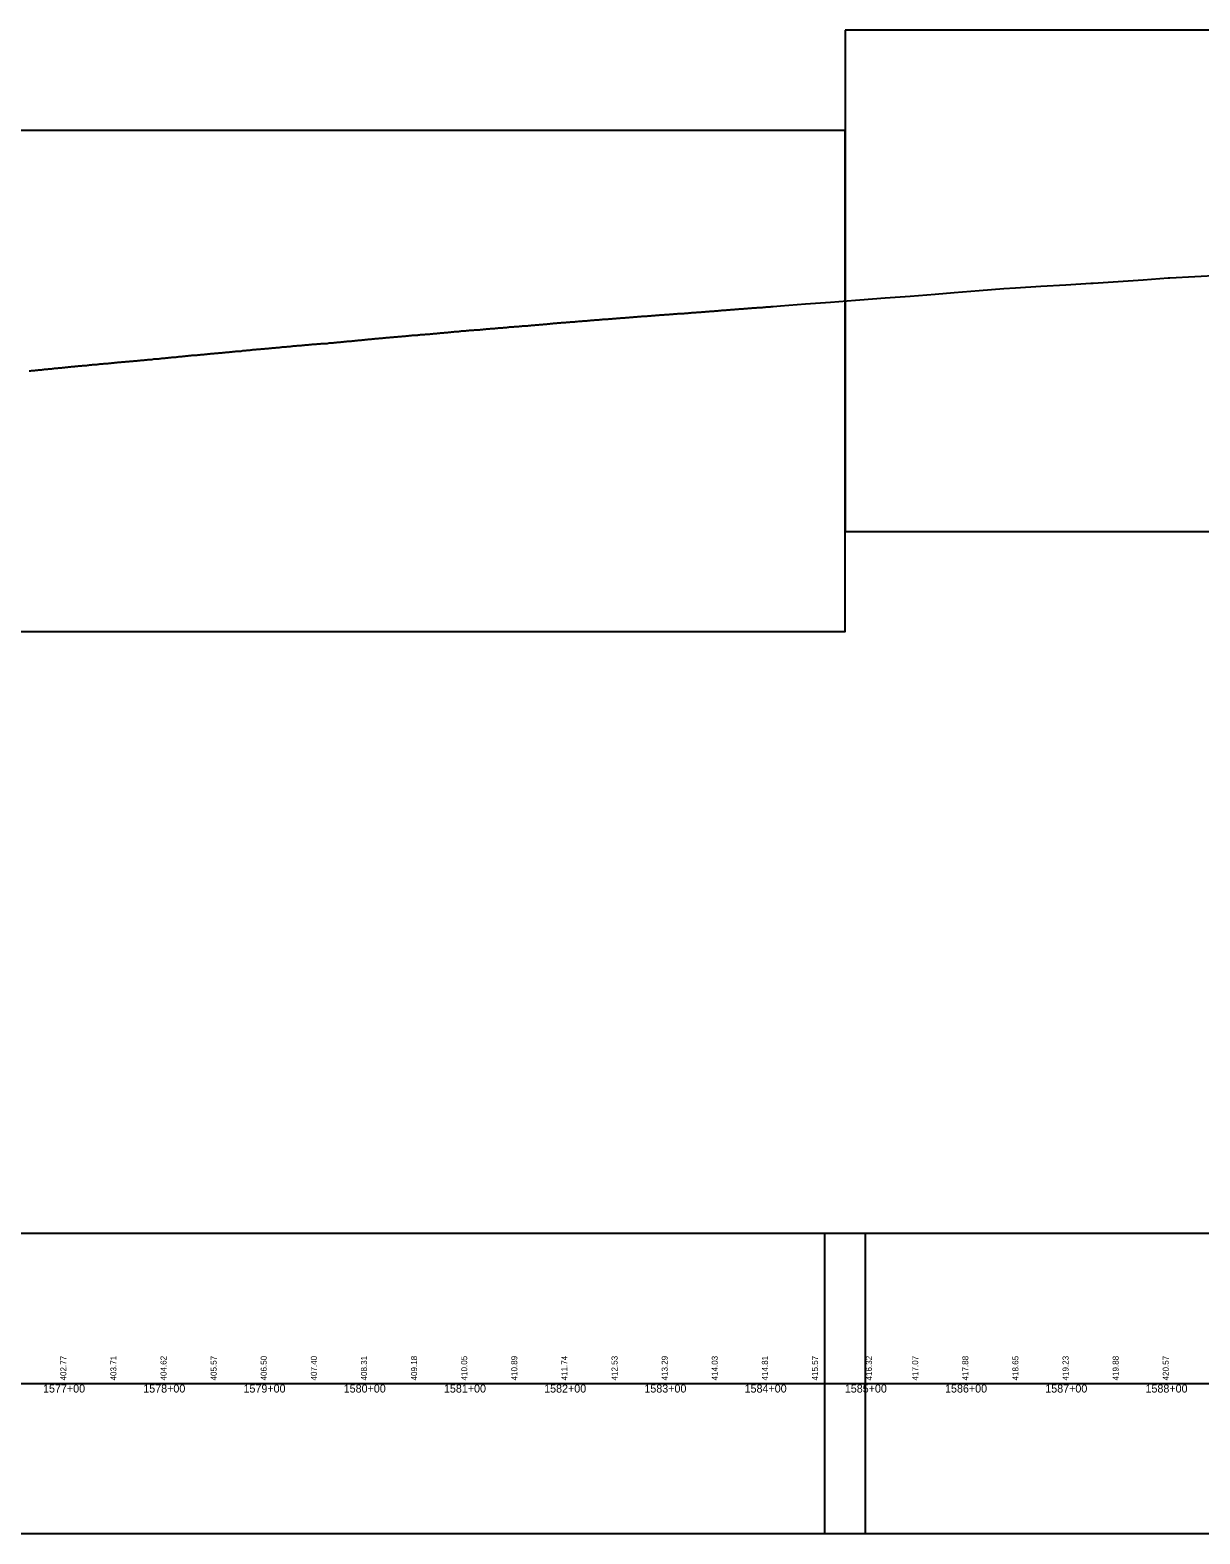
# Model space of a CAD drawing. Extents: x -3627 to 47473, y 2850 to 4350.
# Drawn here: x 45140 to 46307, y 2850 to 4350 of the extents above; entities that cross this region are included whole.
import ezdxf

# ---------------------------------------------------------------- set-up
doc = ezdxf.new("R2010")
doc.units = 0
for name, color, linetype in [('RD_DDB_Profile_EX', 7, 'Continuous'), ('RD_DDB_StaTX', 7, 'Continuous'), ('RD_DDB_StripGrade', 7, 'Continuous'), ('RD_GPK_Profile_Cell', 7, 'Continuous'), ('RD_SHT_ShtClip', 7, 'Continuous')]:
    doc.layers.add(name, color=color, linetype=linetype)

msp = doc.modelspace()

# ---------------------------------------------------------------- linework, layer by layer
at = {"layer": 'RD_DDB_Profile_EX'}
for points in [[(45795.550002, 4067.69308), (45796.552306, 4067.794065), (45797.554121, 4067.893445), (45798.555935, 4067.94337), (45799.547767, 4068.09222), (45800.549582, 4068.14269), (45801.551396, 4068.24261), (45802.5537, 4068.29309), (45803.555515, 4068.34301), (45804.547341, 4068.3935), (45805.549161, 4068.492335), (45806.550976, 4068.64169), (45807.55279, 4068.643275), (45808.555094, 4068.64372), (45809.54692, 4068.742095), (45810.54874, 4068.889875), (45811.550555, 4068.94299), (45812.55237, 4068.992905), (45813.554184, 4069.09282), (45814.5465, 4069.144365), (45815.548319, 4069.24378), (45816.550134, 4069.29423), (45817.551949, 4069.393625), (45818.553764, 4069.493015), (45819.54559, 4069.592965), (45820.547899, 4069.593455), (45821.549713, 4069.64388), (45822.551528, 4069.793285), (45823.553343, 4069.843205), (45824.545274, 4069.89368), (45825.546989, 4069.99361), (45826.549293, 4070.09356), (45827.551107, 4070.14398), (45828.552922, 4070.243395), (45829.54485, 4070.242835), (45830.546568, 4070.491195), (45831.548383, 4070.541085), (45832.550686, 4070.543665), (45833.552501, 4070.593585), (45834.544427, 4070.74254), (45835.546147, 4070.792955), (45836.547962, 4070.892355), (45837.549777, 4070.94226), (45838.551591, 4071.043205), (45839.543523, 4071.14316), (45840.545726, 4071.144135), (45841.547541, 4071.24406), (45842.549356, 4071.39348), (45843.551171, 4071.49238), (45844.543099, 4071.542835), (45845.544812, 4071.64223), (45846.546632, 4071.69214), (45847.548446, 4071.792045), (45848.550261, 4071.79356), (45849.542196, 4071.94189), (45850.543902, 4072.04125), (45851.545723, 4072.092815), (45852.547538, 4072.190495), (45853.54984, 4072.2906), (45854.541772, 4072.342635), (45855.543481, 4072.44255), (45856.545301, 4072.492465), (45857.547116, 4072.492375), (45858.548931, 4072.543385), (45859.550746, 4072.692195), (45860.542685, 4072.8399), (45861.544393, 4072.94036), (45862.546208, 4072.9414), (45863.548023, 4072.9413), (45864.549838, 4073.090035), (45865.542261, 4073.1918), (45866.543972, 4073.14337), (45867.545787, 4073.193295), (45868.547602, 4073.34265), (45869.549417, 4073.391995), (45870.541358, 4073.39252), (45871.543064, 4073.54128), (45872.544879, 4073.641185), (45873.546694, 4073.740495), (45874.548509, 4073.840395), (45875.540456, 4073.840935), (45876.542156, 4073.99024), (45877.544457, 4074.04083), (45878.546272, 4074.09073), (45879.548087, 4074.14121), (45880.540032, 4074.191745), (45881.594843, 4074.294045), (45888.780672, 4074.97893), (45913.763005, 4076.852285), (45938.745129, 4078.72374), (45963.647427, 4080.5908), (45968.230105, 4080.934145), (45993.281873, 4082.81585), (46018.333033, 4084.69476), (46043.278015, 4086.56593), (46062.121382, 4088.14348), (46087.023542, 4090.238335), (46111.893097, 4092.339635), (46123.551462, 4093.019715), (46148.601326, 4094.48206), (46173.651147, 4095.943915)], [(46173.651147, 4095.943915), (46198.528244, 4097.394905), (46200.927912, 4097.56048), (46225.893705, 4099.29392), (46250.859283, 4101.032775), (46275.748102, 4102.767855), (46277.398266, 4102.858735), (46302.414492, 4104.257475), (46327.430679, 4105.65699)], [(45695.564334, 4060.14384), (45696.556229, 4060.24377), (45697.558045, 4060.29436), (45698.559789, 4060.34426), (45699.561603, 4060.543425), (45700.563418, 4060.59368), (45701.555319, 4060.59399), (45702.557135, 4060.693505), (45703.558873, 4060.89301), (45704.560687, 4060.9925), (45705.562502, 4060.99318), (45706.554892, 4061.04422), (45707.556708, 4061.09412), (45708.55852, 4061.193635), (45709.560259, 4061.293525), (45710.562074, 4061.44303), (45711.563888, 4061.54252), (45712.555794, 4061.592445), (45713.557609, 4061.49475), (45714.559343, 4061.545485), (45715.561157, 4061.793745), (45716.562971, 4061.794075), (45717.554887, 4061.8936), (45718.556703, 4062.042635), (45719.558431, 4062.093405), (45720.560245, 4062.142865), (45721.562059, 4062.24231), (45722.553976, 4062.3427), (45723.555797, 4062.392605), (45724.557519, 4062.44297), (45725.559825, 4062.5931), (45726.561639, 4062.69256), (45727.553554, 4062.643375), (45728.555369, 4062.744175), (45729.557094, 4062.94273), (45730.558913, 4062.992175), (45731.560728, 4063.04253), (45732.552648, 4063.09341), (45733.554463, 4063.14332), (45734.556183, 4063.24323), (45735.557997, 4063.29363), (45736.559816, 4063.343555), (45737.551742, 4063.294505), (45738.553558, 4063.542915), (45739.555272, 4063.64231), (45740.557086, 4063.741695), (45741.558901, 4063.791595), (45742.550838, 4063.8426), (45743.553135, 4063.89312), (45744.554851, 4063.99253), (45745.556666, 4064.09193), (45746.55848, 4064.19183), (45747.560295, 4064.24224), (45748.55223, 4064.292195), (45749.553941, 4064.342625), (45750.555755, 4064.491465), (45751.55757, 4064.541365), (45752.559384, 4064.541805), (45753.55132, 4064.6912), (45754.553025, 4064.741655), (45755.554845, 4064.791565), (45756.55666, 4064.84204), (45757.558475, 4064.94195), (45758.550417, 4064.991895), (45759.552116, 4065.09122), (45760.55393, 4065.190535), (45761.555751, 4065.241035), (45762.558054, 4065.291595), (45763.549993, 4065.44041), (45764.551695, 4065.49144), (45765.55351, 4065.54192), (45766.555324, 4065.690665), (45767.557145, 4065.74116), (45768.549089, 4065.841105), (45769.550786, 4065.891005), (45770.5526, 4065.99091), (45771.554415, 4065.991425), (45772.556718, 4066.04252), (45773.54866, 4066.141895), (45774.550365, 4066.24181), (45775.55218, 4066.292315), (45776.553994, 4066.39163), (45777.555809, 4066.442145), (45778.548237, 4066.492665), (45779.549938, 4066.59258), (45780.551759, 4066.69135), (45781.553574, 4066.791255), (45782.555388, 4066.892335), (45783.547333, 4066.89229), (45784.549518, 4066.94277), (45785.551333, 4067.04325), (45786.553153, 4067.14261), (45787.554968, 4067.24195), (45788.546909, 4067.243055), (45789.548608, 4067.29415), (45790.550912, 4067.393975), (45791.552727, 4067.443905), (45792.554541, 4067.44383), (45793.546486, 4067.64267), (45794.548188, 4067.643155), (45795.550002, 4067.69308)], [(45495.58667, 4043.24257), (45496.58897, 4043.293195), (45497.590785, 4043.2939), (45498.582612, 4043.443435), (45499.584913, 4043.59328), (45500.586728, 4043.643165), (45501.588543, 4043.693435), (45502.590359, 4043.793325), (45503.582671, 4043.993295), (45504.584487, 4044.092815), (45505.586302, 4044.09342), (45506.588117, 4044.143675), (45507.590419, 4044.24397), (45508.582314, 4044.393905), (45509.584061, 4044.444135), (45510.586364, 4044.494455), (45511.588179, 4044.594025), (45512.580069, 4044.74205), (45513.581885, 4044.74286), (45514.584127, 4044.79512), (45515.585942, 4044.944425), (45516.587757, 4045.044605), (45517.579644, 4045.14423), (45518.58194, 4045.24494), (45519.583702, 4045.29509), (45520.585517, 4045.394695), (45521.587821, 4045.54516), (45522.579697, 4045.595085), (45523.581513, 4045.59496), (45524.583278, 4045.695605), (45525.585093, 4045.79523), (45526.586908, 4045.845115), (45527.578789, 4045.89615), (45528.580606, 4046.144655), (45529.582364, 4046.244245), (45530.584669, 4046.24574), (45531.586484, 4046.345375), (45532.578362, 4046.39531), (45533.580178, 4046.44573), (45534.58194, 4046.54535), (45535.583758, 4046.645525), (45536.585573, 4046.74514), (45537.577457, 4046.845075), (45538.579274, 4046.84556), (45539.58103, 4046.995465), (45540.582845, 4047.04537), (45541.58466, 4047.14527), (45542.57655, 4047.2449), (45543.578366, 4047.294145), (45544.580117, 4047.394695), (45545.581932, 4047.494255), (45546.584235, 4047.545485), (45547.576123, 4047.695125), (45548.577939, 4047.795025), (45549.579692, 4047.89492), (45550.581507, 4047.945145), (45551.583322, 4048.044715), (45552.575215, 4048.144325), (45553.577035, 4048.19388), (45554.578782, 4048.34342), (45555.580597, 4048.394355), (45556.582412, 4048.494255), (45557.574311, 4048.594195), (45558.576127, 4048.694095), (45559.577872, 4048.793995), (45560.579687, 4048.942365), (45561.581503, 4049.04263), (45562.573886, 4049.04373), (45563.575703, 4049.19397), (45564.577447, 4049.2935), (45565.579262, 4049.343385), (45566.581081, 4049.44328), (45567.572983, 4049.49472), (45568.574799, 4049.543865), (45569.576538, 4049.79298), (45570.578353, 4049.892865), (45571.580168, 4049.943155), (45572.57208, 4049.94472), (45573.573814, 4049.945465), (45574.575629, 4050.044975), (45575.577444, 4050.194475), (45576.579259, 4050.29396), (45577.571651, 4050.2453), (45578.573392, 4050.54403), (45579.575207, 4050.543935), (45580.577022, 4050.64343), (45581.578837, 4050.693745), (45582.570748, 4050.74411), (45583.572479, 4050.84402), (45584.574294, 4050.944365), (45585.576114, 4050.994285), (45586.577929, 4051.093315), (45587.579744, 4051.144575), (45588.571571, 4051.144985), (45589.573386, 4051.39399), (45590.575202, 4051.39391), (45591.577022, 4051.493355), (45592.578837, 4051.593265), (45593.571149, 4051.69338), (45594.572964, 4051.792835), (45595.57478, 4051.94228)], [(45595.57478, 4051.94228), (45596.576595, 4051.943555), (45597.578322, 4051.943935), (45598.570241, 4051.99436), (45599.572057, 4052.292375), (45600.573872, 4052.29324), (45601.575687, 4052.392175), (45602.577404, 4052.44207), (45603.569329, 4052.49251), (45604.57115, 4052.59293), (45605.572965, 4052.692325), (45606.575265, 4052.743355), (45607.576984, 4052.842785), (45608.568907, 4052.99176), (45609.570722, 4053.042145), (45610.572543, 4053.042545), (45611.574843, 4053.142635), (45612.576565, 4053.29207), (45613.568485, 4053.341535), (45614.5703, 4053.39142), (45615.572116, 4053.49179), (45616.573838, 4053.59169), (45617.566247, 4053.69236), (45618.568063, 4053.842255), (45619.569878, 4053.842605), (45620.571693, 4053.892505), (45621.573414, 4054.040505), (45622.565821, 4054.142165), (45623.56764, 4054.19294), (45624.569456, 4054.24284), (45625.571271, 4054.342285), (45626.572995, 4054.342635), (45627.565399, 4054.49243), (45628.567214, 4054.59146), (45629.569034, 4054.642205), (45630.570849, 4054.69253), (45631.572575, 4054.841975), (45632.564491, 4054.94191), (45633.566792, 4054.992575), (45634.568607, 4055.14246), (45635.570427, 4055.043625), (45636.572156, 4055.04396), (45637.564069, 4055.292605), (45638.56637, 4055.39363), (45639.568185, 4055.443935), (45640.569918, 4055.54343), (45641.571732, 4055.74249), (45642.563642, 4055.743265), (45643.565458, 4055.79359), (45644.567759, 4055.893755), (45645.569575, 4055.943655), (45646.571309, 4056.043555), (45647.563216, 4056.0939), (45648.565032, 4056.193805), (45649.56733, 4056.294355), (45650.569145, 4056.39426), (45651.570883, 4056.44494), (45652.562787, 4056.5445), (45653.564602, 4056.59481), (45654.566905, 4056.695295), (45655.56872, 4056.79521), (45656.57046, 4056.944375), (45657.562361, 4057.043945), (45658.564176, 4057.094225), (45659.565991, 4057.19413), (45660.568295, 4057.29433), (45661.560121, 4057.39463), (45662.561936, 4057.49417), (45663.563751, 4057.642955), (45664.565562, 4057.69283), (45665.567867, 4057.694555), (45666.559762, 4057.84381), (45667.561508, 4057.894745), (45668.563323, 4057.945005), (45669.565138, 4058.09455), (45670.566953, 4058.193715), (45671.559335, 4058.244395), (45672.561084, 4058.34395), (45673.562898, 4058.39315), (45674.564713, 4058.445115), (45675.566528, 4058.495025), (45676.558908, 4058.644955), (45677.56066, 4058.74453), (45678.562474, 4058.79475), (45679.564286, 4058.89431), (45680.5661, 4058.9942), (45681.558478, 4059.04518), (45682.560233, 4059.045695), (45683.562047, 4059.14592), (45684.563862, 4059.245835), (45685.565676, 4059.345095), (45686.557569, 4059.44504), (45687.559868, 4059.4956), (45688.561624, 4059.595205), (45689.563438, 4059.64541), (45690.565253, 4059.695625), (45691.557142, 4059.84494), (45692.558958, 4059.94419), (45693.560705, 4059.99407), (45694.562519, 4060.04429), (45695.564334, 4060.14384)], [(45395.605985, 4034.19104), (45396.59794, 4034.33906), (45397.599756, 4034.2909), (45398.601571, 4034.490155), (45399.603387, 4034.54006), (45400.605559, 4034.689985), (45401.597517, 4034.789935), (45402.599332, 4034.88729), (45403.601148, 4034.93973), (45404.602964, 4034.98963), (45405.604649, 4035.08953), (45406.596607, 4035.288155), (45407.598429, 4035.387385), (45408.600245, 4035.388605), (45409.602061, 4035.489175), (45410.604229, 4035.53976), (45411.596183, 4035.6397), (45412.597999, 4035.7396), (45413.599821, 4035.83885), (45414.601637, 4035.98742), (45415.60332, 4036.039305), (45416.59528, 4036.04059), (45417.597096, 4036.089825), (45418.598912, 4036.237675), (45419.600596, 4036.438955), (45420.602899, 4036.440845), (45421.594857, 4036.589475), (45422.596672, 4036.63871), (45423.598488, 4036.639945), (45424.600169, 4036.78782), (45425.60199, 4036.83908), (45426.593954, 4036.98765), (45427.595769, 4037.037535), (45428.597585, 4037.137425), (45429.59926, 4037.18731), (45430.601563, 4037.238635), (45431.59353, 4037.28858), (45432.595346, 4037.38983), (45433.597162, 4037.441105), (45434.59884, 4037.491025), (45435.600654, 4037.54094), (45436.602469, 4037.54156), (45437.594443, 4037.7887), (45438.596259, 4037.937885), (45439.597932, 4037.98706), (45440.599746, 4037.990575), (45441.602048, 4038.041735), (45442.594013, 4038.191), (45443.595836, 4038.290925), (45444.597511, 4038.391545), (45445.599326, 4038.48863), (45446.60114, 4038.63566), (45447.59359, 4038.68915), (45448.595405, 4038.838365), (45449.59709, 4038.83965), (45450.598905, 4038.94025), (45451.59135, 4039.040795), (45452.593166, 4039.188055), (45453.594848, 4039.2366), (45454.596663, 4039.29053), (45455.598972, 4039.34169), (45456.590927, 4039.540355), (45457.592743, 4039.59091), (45458.594916, 4039.64142), (45459.596731, 4039.790095), (45460.598545, 4039.84062), (45461.590503, 4039.939945), (45462.592799, 4040.13875), (45463.594496, 4040.18923), (45464.59631, 4040.28972), (45465.588258, 4040.389655), (45466.590555, 4040.44085), (45467.592376, 4040.59018), (45468.594075, 4040.640655), (45469.59589, 4040.790555), (45470.588316, 4040.743385), (45471.590131, 4040.99108), (45472.591947, 4041.090415), (45473.594145, 4041.19052), (45474.595959, 4041.29094), (45475.587892, 4041.44034), (45476.589708, 4041.49077), (45477.592006, 4041.541895), (45478.593719, 4041.641795), (45479.595534, 4041.741175), (45480.587464, 4041.839545), (45481.589762, 4041.890765), (45482.591578, 4042.04163), (45483.593294, 4042.190525), (45484.585704, 4042.240815), (45485.587519, 4042.34162), (45486.589335, 4042.39103), (45487.591151, 4042.492345), (45488.593362, 4042.542935), (45489.585277, 4042.59332), (45490.587092, 4042.643225), (45491.588908, 4042.79313), (45492.591208, 4042.94284), (45493.592938, 4043.042735), (45494.584854, 4043.092675), (45495.58667, 4043.24257)], [(45195.634709, 4015.54717), (45196.636524, 4015.59725), (45197.638304, 4015.74678), (45198.640118, 4015.846865), (45199.631983, 4015.946805), (45200.633311, 4016.04576), (45201.635126, 4016.146165), (45202.636892, 4016.295285), (45203.638706, 4016.29517), (45204.6301, 4016.39464), (45205.631915, 4016.54421), (45206.633665, 4016.54541), (45207.635483, 4016.79399), (45208.637297, 4016.843535), (45209.638618, 4016.94337), (45210.630523, 4016.944095), (45211.632258, 4017.044), (45212.634077, 4017.1931), (45213.636384, 4017.292985), (45214.638198, 4017.34324), (45215.6301, 4017.343935), (45216.631842, 4017.49307), (45217.633657, 4017.592955), (45218.635964, 4017.644325), (45219.627861, 4017.644985), (45220.629677, 4017.844165), (45221.631422, 4017.9937), (45222.63373, 4018.09499), (45223.635544, 4018.244555), (45224.627439, 4018.2945), (45225.629254, 4018.394395), (45226.631002, 4018.4943), (45227.63331, 4018.59489), (45228.635124, 4018.645115), (45229.627016, 4018.74473), (45230.628832, 4018.84429), (45231.631076, 4018.944925), (45232.63289, 4019.04451), (45233.634704, 4019.144395), (45234.626593, 4019.19433), (45235.628412, 4019.295185), (45236.630656, 4019.296305), (45237.63247, 4019.395935), (45238.624355, 4019.49559), (45239.62617, 4019.645495), (45240.628422, 4019.696315), (45241.630236, 4019.746495), (45242.63205, 4019.846135), (45243.623932, 4019.995805), (45244.625748, 4020.09571), (45245.628002, 4020.196265), (45246.629816, 4020.246425), (45247.63163, 4020.396075), (45248.623509, 4020.44602), (45249.625811, 4020.54635), (45250.627579, 4020.646715), (45251.629394, 4020.746385), (45252.621271, 4020.846335), (45253.623087, 4020.89649), (45254.625388, 4020.99722), (45255.62716, 4021.04736), (45256.628974, 4021.09751), (45257.620846, 4021.29701), (45258.623148, 4021.397295), (45259.624964, 4021.547005), (45260.626738, 4021.547325), (45261.628552, 4021.547665), (45262.620421, 4021.69741), (45263.622724, 4021.94732), (45264.624539, 4021.997405), (45265.626316, 4021.9977), (45266.628131, 4022.14723), (45267.619997, 4022.14758), (45268.6223, 4022.198025), (45269.624115, 4022.44761), (45270.625895, 4022.49734), (45271.617757, 4022.596745), (45272.620061, 4022.69799), (45273.621876, 4022.7479), (45274.623692, 4022.897495), (45275.625476, 4022.997395), (45276.617335, 4022.998005), (45277.619639, 4023.14845), (45278.621454, 4023.347965), (45279.623269, 4023.39787), (45280.625055, 4023.497775), (45281.6174, 4023.69805), (45282.619216, 4023.74805), (45283.621031, 4023.84794), (45284.622846, 4023.89796), (45285.624661, 4023.898125), (45286.616978, 4023.998685), (45287.618793, 4024.198195), (45288.620608, 4024.24808), (45289.622423, 4024.348075), (45290.614273, 4024.49778), (45291.616065, 4024.54803), (45292.61788, 4024.598055), (45293.619695, 4024.697825), (45294.62151, 4024.847725), (45295.613366, 4024.94752)], [(45295.613366, 4024.94752), (45296.615152, 4024.99756), (45297.616969, 4025.197305), (45298.618784, 4025.24736), (45299.620599, 4025.347085), (45300.612461, 4025.497025), (45301.614241, 4025.596735), (45302.616056, 4025.64643), (45303.617871, 4025.696505), (45304.619686, 4025.79639), (45305.611554, 4025.796525), (45306.613328, 4025.84663), (45307.615143, 4026.09653), (45308.616959, 4026.09687), (45309.618774, 4026.146555), (45310.610647, 4026.246265), (45311.612416, 4026.445685), (45312.614231, 4026.49606), (45313.616046, 4026.54596), (45314.617861, 4026.695855), (45315.60974, 4026.795535), (45316.611503, 4026.895425), (45317.613318, 4026.94532), (45318.615133, 4026.99521), (45319.616949, 4027.1451), (45320.608836, 4027.24475), (45321.610593, 4027.294935), (45322.612409, 4027.394825), (45323.614224, 4027.49472), (45324.616039, 4027.59461), (45325.60793, 4027.744225), (45326.609681, 4027.793785), (45327.611496, 4027.89333), (45328.613312, 4027.99354), (45329.615127, 4027.99377), (45330.607023, 4028.09405), (45331.608772, 4028.19395), (45332.610588, 4028.34348), (45333.612403, 4028.4441), (45334.614218, 4028.494375), (45335.606121, 4028.59394), (45336.60786, 4028.743455), (45337.609676, 4028.793735), (45338.611495, 4028.89324), (45339.61331, 4029.04273), (45340.605218, 4029.092665), (45341.606952, 4029.142965), (45342.608768, 4029.242855), (45343.610583, 4029.44232), (45344.612399, 4029.542205), (45345.604317, 4029.592145), (45346.606045, 4029.642475), (45347.60786, 4029.79192), (45348.609676, 4029.891805), (45349.611007, 4029.84142), (45350.602936, 4029.84339), (45351.60465, 4030.19073), (45352.60647, 4030.241145), (45353.608286, 4030.34104), (45354.610101, 4030.39093), (45355.601928, 4030.541405), (45356.603744, 4030.69076), (45357.605559, 4030.741205), (45358.607375, 4030.8411), (45359.609196, 4030.89157), (45360.601023, 4030.942645), (45361.602838, 4031.09199), (45362.604654, 4031.290745), (45363.60647, 4031.390645), (45364.608285, 4031.441135), (45365.600112, 4031.49108), (45366.601934, 4031.590995), (45367.603749, 4031.6409), (45368.605565, 4031.740805), (45369.607862, 4031.84135), (45370.609562, 4031.941255), (45371.601505, 4032.0412), (45372.603321, 4032.141105), (45373.605142, 4032.14162), (45374.606958, 4032.29032), (45375.608651, 4032.39022), (45376.6006, 4032.44139), (45377.602416, 4032.49192), (45378.604232, 4032.59121), (45379.606529, 4032.64054), (45380.608231, 4032.741645), (45381.600177, 4032.93979), (45382.601993, 4032.940895), (45383.603809, 4032.942025), (45384.605624, 4033.190085), (45385.607315, 4033.24061), (45386.599267, 4033.339925), (45387.601089, 4033.44047), (45388.602905, 4033.441015), (45389.605201, 4033.592135), (45390.606895, 4033.790215), (45391.598844, 4033.890155), (45392.60066, 4033.940675), (45393.602475, 4033.99058), (45394.604297, 4034.090495), (45395.605985, 4034.19104)], [(45139.260847, 4010.08968), (45140.255024, 4010.189695), (45140.653121, 4010.241205), (45141.654818, 4010.29191), (45142.655227, 4010.34309), (45143.656923, 4010.542025), (45144.65862, 4010.59267), (45145.650378, 4010.692155), (45146.652075, 4010.79224), (45147.652481, 4010.89238), (45148.654177, 4010.992975), (45149.655874, 4011.093555), (45150.647632, 4011.143105), (45151.648035, 4011.194205), (45152.649731, 4011.44296), (45153.651427, 4011.543055), (45154.653124, 4011.64315), (45155.65482, 4011.742825), (45156.645282, 4011.79471), (45157.646968, 4011.894425), (45158.648665, 4012.04415), (45159.650361, 4012.095325), (45160.652057, 4012.19505), (45161.642517, 4012.245665), (45162.644213, 4012.34575), (45163.645909, 4012.445835), (45164.647606, 4012.645625), (45165.649302, 4012.74543), (45166.649697, 4012.79618), (45167.641461, 4012.79694), (45168.643157, 4012.99633), (45169.644853, 4013.145975), (45170.646549, 4013.196305), (45171.646906, 4013.24727), (45172.638697, 4013.347325), (45173.640397, 4013.44742), (45174.642093, 4013.547515), (45175.64248, 4013.747945), (45176.644155, 4013.84816), (45177.635932, 4013.84842), (45178.63763, 4013.998425), (45179.639325, 4014.09861), (45180.639708, 4014.19933), (45181.641396, 4014.349365), (45182.643093, 4014.399535), (45183.634856, 4014.49959), (45184.636551, 4014.599675), (45185.017021, 4014.619015), (45185.637515, 4014.6495), (45186.63933, 4014.649475), (45187.641136, 4014.699475), (45188.632971, 4014.99924), (45189.634786, 4014.999245), (45190.63611, 4015.04875), (45191.637926, 4015.19845), (45192.639718, 4015.348015), (45193.641532, 4015.39803), (45194.633383, 4015.44797), (45195.634709, 4015.54717)]]:
    msp.add_lwpolyline(points, dxfattribs=at)
at = {"layer": 'RD_GPK_Profile_Cell'}
msp.add_line((1000, 3000), (46705.077602, 3000), dxfattribs=at)
at = {"layer": 'RD_SHT_ShtClip'}
for points in [[(45953.33, 4350), (45953.33, 3850), (47453.33, 3850), (47453.33, 3850), (47453.33, 4350), (47453.33, 4350)], [(44453.33, 4250), (44453.33, 3750), (45953.33, 3750), (45953.33, 3750), (45953.33, 4250), (45953.33, 4250)], [(44433.33, 3150), (45973.33, 3150), (45973.33, 2850), (44433.33, 2850)], [(45933.33, 3150), (47473.33, 3150), (47473.33, 2850), (45933.33, 2850)]]:
    msp.add_lwpolyline(points, close=True, dxfattribs=at)

# ---------------------------------------------------------------- texts
at = {"layer": 'RD_DDB_StaTX'}
for s, p in [('1577+00', (45153.125471, 2991)), ('1578+00', (45253.125471, 2991)), ('1579+00', (45353.125471, 2991)), ('1580+00', (45453.125471, 2991)), ('1581+00', (45553.125471, 2991)), ('1582+00', (45653.125471, 2991)), ('1583+00', (45753.125471, 2991)), ('1584+00', (45853.125471, 2991)), ('1585+00', (45953.125471, 2991)), ('1586+00', (46053.125471, 2991)), ('1587+00', (46153.125471, 2991)), ('1588+00', (46253.125471, 2991))]:
    msp.add_text(s, height=8, dxfattribs=at).set_placement(p)
at = {"layer": 'RD_DDB_StripGrade'}
for s, p in [('402.77', (45176.33, 3003.073688)), ('403.71', (45226.33, 3003.073688)), ('404.62', (45276.33, 3003.073688)), ('405.57', (45326.33, 3003.073688)), ('406.50', (45376.33, 3003.073688)), ('407.40', (45426.33, 3003.073688)), ('408.31', (45476.33, 3003.073688)), ('409.18', (45526.33, 3003.073688)), ('410.05', (45576.33, 3003.073688)), ('410.89', (45626.33, 3003.073688)), ('411.74', (45676.33, 3003.073688)), ('412.53', (45726.33, 3003.073688)), ('413.29', (45776.33, 3003.073688)), ('414.03', (45826.33, 3003.073688)), ('414.81', (45876.33, 3003.073688)), ('415.57', (45926.33, 3003.073688)), ('416.32', (45980.188107, 3003.073688)), ('417.07', (46026.33, 3003.073688)), ('417.88', (46076.33, 3003.073688)), ('418.65', (46126.33, 3003.073688)), ('419.23', (46176.33, 3003.073688)), ('419.88', (46226.33, 3003.073688)), ('420.57', (46276.33, 3003.073688))]:
    msp.add_text(s, height=6, rotation=90, dxfattribs=at).set_placement(p)

doc.saveas('drawing.dxf')
